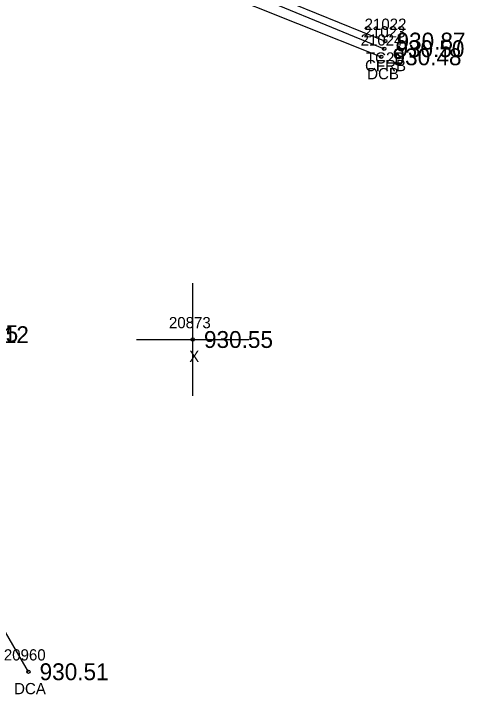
# Model space of a CAD drawing. Extents: x 1576181 to 1577685, y 1099396 to 1101490.
# Drawn here: x 1576786.7 to 1576826.8, y 1100065.9 to 1100126.4 of the extents above; entities that cross this region are included whole.
import ezdxf

# ---------------------------------------------------------------- set-up
doc = ezdxf.new("R2010")
doc.units = 0
for name, color, linetype in [('RD_DTM_BkLn2', 7, 'Continuous'), ('RD_EX_Conc', 7, 'Continuous'), ('RD_EX_Conc_txCode', 7, 'Continuous'), ('RD_EX_Misc', 7, 'Continuous'), ('RD_EX_Misc_txCode', 7, 'Continuous'), ('RD_EX_TX_Conc_ELEV', 7, 'Continuous'), ('RD_EX_TX_Misc_ELEV', 7, 'Continuous'), ('RD_SMD_Locator', 7, 'Continuous')]:
    doc.layers.add(name, color=color, linetype=linetype)

msp = doc.modelspace()

# ---------------------------------------------------------------- linework, layer by layer
at = {"layer": 'RD_DTM_BkLn2'}
msp.add_lwpolyline([(1576787.859, 1100142.151), (1576789.652, 1100140.36), (1576797.464, 1100134.51), (1576805.466, 1100129.841), (1576819.785, 1100123.998)], dxfattribs=at)
at = {"layer": 'RD_EX_Conc'}
for points in [[(1576785.777, 1100195.961), (1576786.17, 1100195.752), (1576783.397, 1100187.603), (1576781.942, 1100181.747), (1576781.056, 1100176.612), (1576780.677, 1100170.531), (1576780.648, 1100154.572), (1576781.71, 1100148.925), (1576783.019, 1100145.98), (1576783.874, 1100142.998), (1576785.927, 1100140.682), (1576788.648, 1100139.275), (1576796.673, 1100133.29), (1576804.546, 1100128.565), (1576819.43, 1100122.601)], [(1576787.42, 1100141.854), (1576789.211, 1100139.996), (1576797.129, 1100133.951), (1576805.141, 1100129.335), (1576819.688, 1100123.321)], [(1576788.055, 1100067.905), (1576777.624, 1100085.825), (1576779.54, 1100090.34), (1576780.968, 1100097.886), (1576779.229, 1100107.288), (1576773.149, 1100115.363), (1576766.472, 1100119.015), (1576757.644, 1100120.82), (1576751.497, 1100121.086), (1576746.531, 1100119.64), (1576742.733, 1100117.064), (1576738.416, 1100112.144)]]:
    msp.add_lwpolyline(points, dxfattribs=at)
at = {"layer": 'RD_EX_Misc'}
for p, q in [((1576802.669, 1100092.456), (1576802.669, 1100102.456)), ((1576797.669, 1100097.456), (1576807.669, 1100097.456))]:
    msp.add_line(p, q, dxfattribs=at)
at = {"layer": 'RD_SMD_Locator'}
for centre in [(1576819.785, 1100123.998), (1576819.688, 1100123.321), (1576819.43, 1100122.601), (1576802.669, 1100097.456), (1576788.055, 1100067.905)]:
    msp.add_circle(centre, 0.15, dxfattribs=at)

# ---------------------------------------------------------------- texts
at = {"layer": 'RD_EX_Conc_txCode'}
for s, p in [('21022', (1576817.95, 1100124.998)), ('21023', (1576817.854, 1100124.321)), ('21024', (1576817.595, 1100123.601)), ('TC2B', (1576818.068, 1100121.998)), ('CFRB', (1576817.988, 1100121.321)), ('DCB', (1576818.178, 1100120.601)), ('20960', (1576785.874, 1100068.905)), ('DCA', (1576786.787, 1100065.905))]:
    msp.add_text(s, height=1, dxfattribs=at).set_placement(p)
at = {"layer": 'RD_EX_Misc_txCode'}
for s, p in [('20873', (1576800.55, 1100098.456)), ('X', (1576802.354, 1100095.456))]:
    msp.add_text(s, height=1, dxfattribs=at).set_placement(p)
at = {"layer": 'RD_EX_TX_Conc_ELEV'}
for s, p in [('930.87', (1576820.785, 1100123.248)), ('930.50', (1576820.688, 1100122.571)), ('930.48', (1576820.43, 1100121.851)), ('930.15', (1576781.014, 1100097.227)), ('930.12', (1576781.968, 1100097.136)), ('930.51', (1576789.055, 1100067.155))]:
    msp.add_text(s, height=1.5, dxfattribs=at).set_placement(p)
at = {"layer": 'RD_EX_TX_Misc_ELEV'}
msp.add_text('930.55', height=1.5, dxfattribs=at).set_placement((1576803.669, 1100096.706))

doc.saveas('drawing.dxf')
